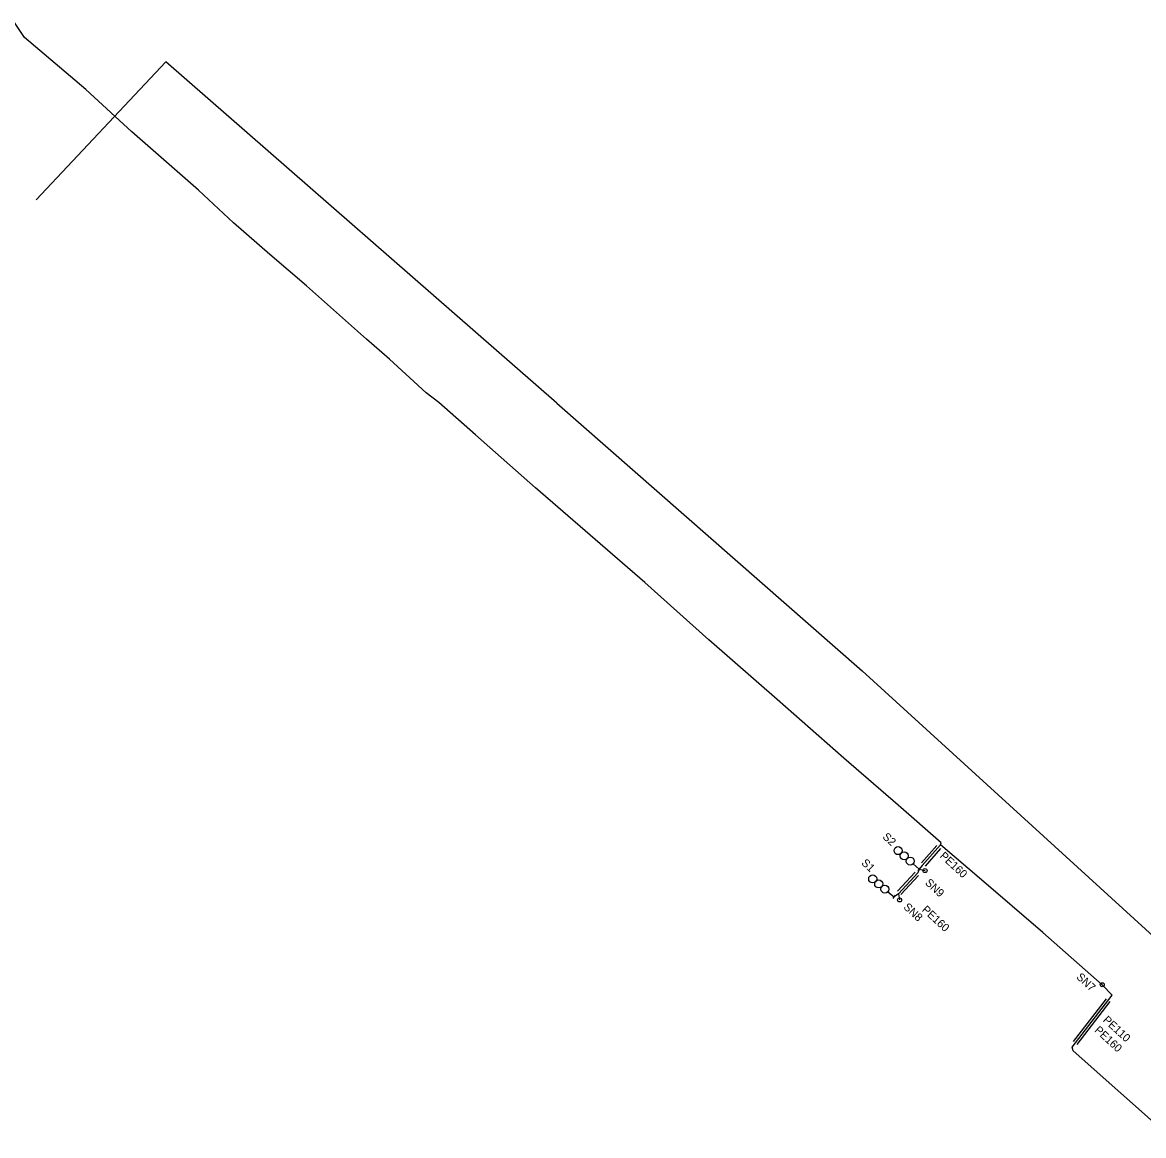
# Model space of a CAD drawing. Extents: x -731967 to -723173, y -945358 to -941505.
# Drawn here: x -726077.8 to -725937.8, y -942250.2 to -942111.1 of the extents above; entities that cross this region are included whole.
import ezdxf

# ---------------------------------------------------------------- set-up
doc = ezdxf.new("R2010")
doc.units = 0
for name, color, linetype in [('Vrstva 2', 7, 'Continuous'), ('Vrstva 28', 7, 'Continuous'), ('Vrstva 35', 7, 'Continuous')]:
    doc.layers.add(name, color=color, linetype=linetype)

msp = doc.modelspace()

# ---------------------------------------------------------------- linework, layer by layer
at = {"layer": 'Vrstva 2'}
for p, q in [((-725966.54, -942216.22), (-725965.79, -942216.88)), ((-725966.54, -942216.22), (-725965.79, -942216.88)), ((-725965.62, -942216.69), (-725965.95, -942217.07)), ((-725965.62, -942216.69), (-725965.95, -942217.07)), ((-725965.07, -942217.07), (-725965.07, -942217.07)), ((-725965.07, -942217.07), (-725965.07, -942217.07)), ((-725969.71, -942219.71), (-725968.94, -942220.35)), ((-725969.71, -942219.71), (-725968.94, -942220.35)), ((-725968.78, -942220.16), (-725969.1, -942220.54)), ((-725968.78, -942220.16), (-725969.1, -942220.54)), ((-725968.24, -942220.74), (-725968.24, -942220.74)), ((-725968.24, -942220.74), (-725968.24, -942220.74))]:
    msp.add_line(p, q, dxfattribs=at)
for points in [[(-725963.59, -942213.93), (-725965.5, -942216.1)], [(-725963.59, -942213.93), (-725965.5, -942216.1)], [(-725963.14, -942214.33), (-725965.06, -942216.5)], [(-725963.14, -942214.33), (-725965.06, -942216.5)], [(-725966.31, -942217.27), (-725968.52, -942219.66)], [(-725966.31, -942217.27), (-725968.52, -942219.66)], [(-725965.87, -942217.68), (-725968.08, -942220.07)], [(-725965.87, -942217.68), (-725968.08, -942220.07)], [(-725946.52, -942238.41), (-725942.4, -942233.07)], [(-725946.52, -942238.41), (-725942.4, -942233.07)], [(-725946.05, -942238.78), (-725941.93, -942233.44)], [(-725946.05, -942238.78), (-725941.93, -942233.44)]]:
    msp.add_lwpolyline(points, dxfattribs=at)
for centre, radius in [((-725968.44, -942214.58), 0.5), ((-725968.44, -942214.58), 0.5), ((-725967.67, -942215.23), 0.5), ((-725967.67, -942215.23), 0.5), ((-725966.92, -942215.89), 0.5), ((-725966.92, -942215.89), 0.5), ((-725965.07, -942217.07), 0.25), ((-725965.07, -942217.07), 0.25), ((-725971.61, -942218.1), 0.5), ((-725971.61, -942218.1), 0.5), ((-725970.86, -942218.74), 0.5), ((-725970.86, -942218.74), 0.5), ((-725970.09, -942219.39), 0.5), ((-725970.09, -942219.39), 0.5), ((-725968.24, -942220.74), 0.25), ((-725968.24, -942220.74), 0.25), ((-725942.92, -942231.33), 0.25), ((-725942.92, -942231.33), 0.25)]:
    msp.add_circle(centre, radius, dxfattribs=at)
at = {"layer": 'Vrstva 28'}
for points in [[(-725968.42, -942208.88), (-725975.23, -942203.01), (-725983.53, -942195.71), (-725992.07, -942188.24), (-726000.06, -942181.08), (-726013.74, -942169.27), (-726021.25, -942162.62), (-726025.8, -942158.61), (-726027.38, -942157.41), (-726031.97, -942153.2), (-726034.85, -942150.68), (-726042.35, -942144.03), (-726046.95, -942140.11), (-726051.48, -942136.17), (-726055.84, -942132.09), (-726064.18, -942124.79), (-726069.91, -942119.51), (-726077.57, -942113.02), (-726078.84, -942111.12)], [(-725968.42, -942208.88), (-725975.23, -942203.01), (-725983.53, -942195.71), (-725992.07, -942188.24), (-726000.06, -942181.08), (-726013.74, -942169.27), (-726021.25, -942162.62), (-726025.8, -942158.61), (-726027.38, -942157.41), (-726031.97, -942153.2), (-726034.85, -942150.68), (-726042.35, -942144.03), (-726046.95, -942140.11), (-726051.48, -942136.17), (-726055.84, -942132.09), (-726064.18, -942124.79), (-726069.91, -942119.51), (-726077.57, -942113.02), (-726078.84, -942111.12)], [(-725934.67, -942250.17), (-725946.58, -942239.58), (-725946.69, -942239.12), (-725941.69, -942232.64), (-725942.92, -942231.33), (-725950.35, -942224.81), (-725958.02, -942218.21), (-725963.12, -942213.85), (-725963.06, -942213.62), (-725968.42, -942208.88)], [(-725934.67, -942250.17), (-725946.58, -942239.58), (-725946.69, -942239.12), (-725941.69, -942232.64), (-725942.92, -942231.33), (-725950.35, -942224.81), (-725958.02, -942218.21), (-725963.12, -942213.85), (-725963.06, -942213.62), (-725968.42, -942208.88)], [(-725963.12, -942213.85), (-725965.41, -942216.45), (-725965.79, -942216.88), (-725965.07, -942217.07)], [(-725963.12, -942213.85), (-725965.41, -942216.45), (-725965.79, -942216.88), (-725965.07, -942217.07)], [(-725965.79, -942216.88), (-725965.98, -942217.36), (-725968.39, -942219.96), (-725968.94, -942220.35)], [(-725965.79, -942216.88), (-725965.98, -942217.36), (-725968.39, -942219.96), (-725968.94, -942220.35)], [(-725968.39, -942219.96), (-725968.24, -942220.74)], [(-725968.39, -942219.96), (-725968.24, -942220.74)]]:
    msp.add_lwpolyline(points, dxfattribs=at)
at = {"layer": 'Vrstva 35'}
for p, q in [((-726059.92, -942116.04), (-726076.11, -942133.27)), ((-726011.07, -942158.67), (-726059.92, -942116.04)), ((-726011.07, -942158.67), (-725972.92, -942192.12)), ((-725972.92, -942192.12), (-725936.09, -942225.67))]:
    msp.add_line(p, q, dxfattribs=at)

# ---------------------------------------------------------------- texts
at = {"layer": 'Vrstva 2'}
for s, rotation, p in [('S2', 316.9881, (-725970.46, -942212.95)), ('S2', 316.9881, (-725970.46, -942212.95)), ('S1', 316.9881, (-725973.1, -942216.22)), ('S1', 316.9881, (-725973.1, -942216.22)), ('PE160', 317.2336, (-725963.3, -942215.35)), ('PE160', 317.2336, (-725963.3, -942215.35)), ('SN9', 316.9881, (-725965.14, -942218.69)), ('SN9', 316.9881, (-725965.14, -942218.69)), ('SN8', 316.9881, (-725967.84, -942221.73)), ('SN8', 316.9881, (-725967.84, -942221.73)), ('PE160', 317.2336, (-725965.54, -942222.07)), ('PE160', 317.2336, (-725965.54, -942222.07)), ('SN7', 316.9881, (-725946.23, -942230.47)), ('SN7', 316.9881, (-725946.23, -942230.47)), ('PE110', 317.2336, (-725942.92, -942235.84)), ('PE110', 317.2336, (-725942.92, -942235.84)), ('PE160', 317.2336, (-725943.97, -942237.11)), ('PE160', 317.2336, (-725943.97, -942237.11))]:
    msp.add_text(s, height=1, rotation=rotation, dxfattribs=at).set_placement(p)

doc.saveas('drawing.dxf')
